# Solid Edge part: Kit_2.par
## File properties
Last saved by: bmolnar
Revision: 76
Dokumentum tartalom típus: 0
Sűrűség: 0,000 kg/m^3
Pontosság: 0,990
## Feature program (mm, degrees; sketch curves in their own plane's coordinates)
base feature "unnamed BaseFeature 1"
sketch for "Furat_1" plane through (-20.15, 0, 96.65) normal (1, 0, 0) x-axis (0, 1, 0)
  hole centre (0, -15.15) bore radius 2.067
hole "Furat_1" nominal diameter 5 finite  StartChamferOffset = 0.6 mm; StartChamferAngle = 45 deg
sketch for "Furat_2" plane through (-13, -13, 83.9) normal (0, 0, 1) x-axis (0, 1, 0)
  hole centre (0, 0) bore radius 2.067
hole "Furat_2" nominal diameter 5
sketch for "unnamed Hole 1" plane through (-13, -13, 83.9) normal (0, 0, 1) x-axis (0, 1, 0)
  hole centre (26, 0) bore radius 2.067
hole "unnamed Hole 1"
sketch for "unnamed Hole 2" plane through (-13, -13, 83.9) normal (0, 0, 1) x-axis (0, 1, 0)
  hole centre (26, -26) bore radius 2.067
hole "unnamed Hole 2"
sketch for "unnamed Hole 3" plane through (-13, -13, 83.9) normal (0, 0, 1) x-axis (0, 1, 0)
  hole centre (0, -26) bore radius 2.067
hole "unnamed Hole 3"
pattern "unnamed Pattern 1" of "Furat_2", "unnamed Hole 1", "unnamed Hole 2", "unnamed Hole 3"
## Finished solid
Body 1: solid body, 265 faces, 630 edges, 376 vertices, 3 internal voids.
  Faces by surface: plane 132, cylinder 56, swept 42, cone 26, torus 9
  Edges by curve: line 381, circle 155, spline 88, curve on surface 5, ellipse 1
Bounding box of the edges (mm; curved faces can reach further): 40.300 x 40.300 x 12.500, from (-20.15, -20.15, 76.5) to (20.15, 20.15, 89).
Cylindrical faces by radius (mm): R0.2 x18, R0.4246 x1, R0.4865 x1, R2.067 x5, R3.75 x2, R4 x4, R4.1 x12, R5.24 x1, R5.45 x2, R5.55 x2, R5.7 x1, R6 x1, R6.92 x1, R7 x1, R13.75 x4
Conical faces (half-angle, radius in mm at the cone's reference point): 0.5 deg R5 x4, 3 deg R6.96 x1, 7 deg R6.4156 x1, 14 deg R5.12 x1, 14 deg R5.3801 x1, 17 deg R5.12 x1, 23 deg R5.7369 x1, 42.5 deg R5.1096 x1, 45 deg R2.317 x2, 45 deg R2.367 x2, 45 deg R2.667 x1, 45 deg R4.25 x2, 45 deg R5.3 x2, 45 deg R5.35 x2, 45 deg R5.85 x1, 84 deg R5.4096 x1, 85 deg R6.73 x1, 87 deg R5.1371 x1
Toroidal faces (ring radius, tube radius in mm): R3.8 r0.2 x2, R4.4 r0.4 x2, R5.6606 r0.18 x1, R6.1131 r0.26 x1, R6.72 r0.2 x1, R9.4957 r0.5 x1, R11.0043 r0.5 x1
Planar faces by outward normal: +x 5, +y 16, +z 17, -x 7, -y 13, -z 5, oblique 69
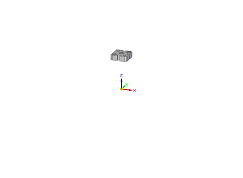
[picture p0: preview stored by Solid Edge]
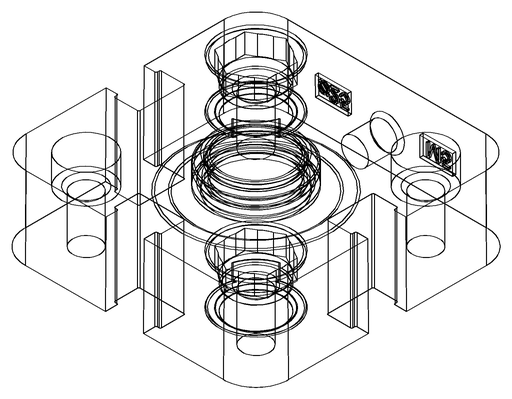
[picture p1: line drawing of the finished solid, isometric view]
